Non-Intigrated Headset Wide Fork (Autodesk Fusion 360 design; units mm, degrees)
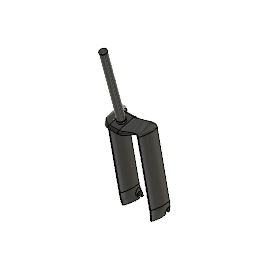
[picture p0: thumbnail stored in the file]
sketch "Sketch1" plane through (0, 0, 0) normal (0, 0, 1) x axis (1, 0, 0)
  circle C1 centre (0, 0) radius 15
  circle C2 centre (0, 0) radius 14.3
  circle C3 centre (0, 0) radius 17
  circle C4 centre (0, 0) radius 12.8
  point P1 (0, 0)
  point P2 (0, 0)
  coincident P1 P2
  concentric C1 C2
  concentric C1 C3
  dimension "d1" diameter C1 = 30
  dimension "d2" diameter C2 = 28.6
  dimension "d3" diameter C3 = 34
  dimension "d76" = -1.5
extrude "Extrude1" new body sketch "Sketch1" profile of C2 along normal blind 300
extrude "Extrude2" add sketch "Sketch1" profile of C1 C2 along normal blind 10
extrude "Extrude3" add sketch "Sketch1" profile of C1 C2 C3 against normal blind 5
sketch "Sketch2" plane through (0, 0, 0) normal (1, 0, 0) x axis (0, 1, 0)
  line L1 (0, -374) -> (0, -5)
  line L2 (35, -374) -> (0, -374)
  point P2 (0, -5)
  point P3 (0, -374)
  point P4 (35, -374)
  vertical L1
  perpendicular L1 L2
  dimension "d10" distance P2 P3 = 369
  dimension "d11" distance P3 P4 = 35
sketch "Sketch3" plane through (0, 0, 0) normal (0, 1, 0) x axis (1, 0, 0)
  line L1 (57.5, 177.3414) -> (57.5, 29.6202)
  line L2 (-57.5, 177.3414) -> (-57.5, 29.6202)
  line L3 (57.5, 320.1385) -> (57.5, 177.3414)
  line L4 (-57.5, 320.1385) -> (-57.5, 177.3414)
  line L5 (-32.5, 5) -> (32.5, 5)
  arc A1 centre (32.5, 29.6202) radius 25 between (57.5, 29.6202) and (32.5, 5)
  arc A2 centre (-32.5, 29.6202) radius 25 between (-32.5, 5) and (-57.5, 29.6202)
  arc A3 centre (112.9167, 320.1385) radius 170.4167 between (-57.5, 320.1385) and (-50, 369.3789)
  arc A4 centre (-112.9167, 320.1385) radius 170.4167 between (50, 369.3789) and (57.5, 320.1385)
  point P2 (-50, 369.3789)
  point P3 (50, 369.3789)
  point P5 (57.5, 177.3414)
  point P6 (-57.5, 177.3414)
  tangent A1 L1
  tangent A2 L2
  tangent L4 A3
  tangent L3 A4
  tangent A2 L5
  dimension "d12" distance P2 P3 = 100
  dimension "d13" distance P5 P6 = 115
work_plane "WorkPlane1" AlongDistance -30
sketch "Sketch4" plane through (0, 0, -30) normal (0, 0, 1) x axis (1, 0, 0)
  line L1 (61.75, -26.0181) -> (65.75, -26.0181)
  arc A1 centre (63.75, 47.577) radius 6.4049 clockwise from (57.5, 48.977) to (70, 48.977)
  arc A2 centre (-64.0291, 18.9545) radius 137.3505 clockwise from (70, 48.977) to (65.75, -26.0181)
  arc A3 centre (191.5291, 18.9545) radius 137.3505 clockwise from (61.75, -26.0181) to (57.5, 48.977)
  point P5 (65.75, -26.0181)
  point P6 (61.75, -26.0181)
  tangent A1 A2
  tangent A1 A3
  dimension "d21" distance P5 P6 = 4
move "Move1"
sweep "Sweep1" sketch "Sketch4" TwistAngle 0 TaperAngle 0
move "Move2"
sketch "Sketch5" plane through (0, 0, 0) normal (1, 0, 0) x axis (0, 1, 0)
  line L1 (30.0985, 8.2412) -> (-32.6867, -8.582)
  line L2 (32.5, -0.1704) -> (-1.2941, -0.1704)
  arc A1 centre (32.4028, -0.3584) radius 8.903 clockwise from (30.0985, 8.2412) to (40, -5)
  arc A2 centre (-30.6379, -16.2282) radius 7.9159 clockwise from (-37.7927, -19.615) to (-32.6867, -8.582)
  arc A3 centre (-30.9882, 158.5102) radius 178.2552 clockwise from (40, -5) to (-37.7927, -19.615)
  point P4 (-1.2941, -0.1704)
  point P2 (-32.6867, -8.582)
  point P3 (30.0985, 8.2412)
  midpoint L1 P4
  horizontal L2
  tangent L1 A1
  tangent L1 A2
  dimension "d28" distance P2 P3 = 65
  dimension "d29" angle L1 L2 = 15
extrude "Extrude4" add sketch "Sketch5" profile of L1 A1 A2 A3 along normal blind 20
loft "Loft1"
sketch "Sketch6" plane through (0, 0, 0) normal (1, 0, 0) x axis (0, 1, 0)
  line L1 (95.5042, -361.4266) -> (0, -5)
  line L2 (369, -5) -> (0, -5)
  line L3 (124.482, -353.6621) -> (95.5042, -361.4266)
  line L4 (126.6058, -378.9749) -> (120.1353, -354.8267)
  line L5 (135.3147, -376.7052) -> (128.8442, -352.5571)
  line L6 (153.8442, -352.5571) -> (128.8442, -352.5571)
  line L7 (126.6058, -378.9749) -> (135.3147, -376.7052)
  line L8 (120.8103, -380.5278) -> (114.3398, -356.3797)
  line L9 (141.0947, -375.0926) -> (134.6242, -350.9445)
  line L10 (120.8103, -380.5278) -> (141.0947, -375.0926)
  circle C1 centre (124.482, -353.6621) radius 4.5
  circle C2 centre (124.482, -353.6621) radius 10.5
  point P5 (124.482, -353.6621)
  point P6 (124.482, -353.6621)
  point P8 (120.1353, -354.8267)
  point P10 (128.8442, -352.5571)
  point P13 (114.3398, -356.3797)
  point P15 (134.6242, -350.9445)
  point P2 (0, -5)
  point P3 (95.5042, -361.4266)
  point P9 (126.6058, -378.9749)
  point P11 (135.3147, -376.7052)
  point P14 (120.8103, -380.5278)
  point P16 (141.0947, -375.0926)
  horizontal L2
  perpendicular L1 L3
  coincident P5 P6
  concentric C1 C2
  coincident C1 P8
  coincident L3 P8
  perpendicular L3 L4
  horizontal L6
  coincident C1 P10
  coincident L3 P13
  coincident C2 P13
  perpendicular L3 L8
  coincident C2 P15
  perpendicular L3 L9
  perpendicular L8 L10
  dimension "d38" distance P2 P3 = 369
  dimension "d39" angle L1 L2 = 75
  dimension "d40" distance P3 P5 = 30
  dimension "d41" diameter C1 = 9
  dimension "d42" diameter C2 = 21
  dimension "d43" distance P8 P9 = 25
  dimension "d44" angle L5 L6 = 75
  dimension "d45" distance P10 P11 = 25
  dimension "d50" distance P13 P14 = 25
  dimension "d51" distance P15 P16 = 25
extrude "Extrude5" cut sketch "Sketch6" profile of C1 C2 L4 L5 L7 along normal blind 80
extrude "Extrude6" cut sketch "Sketch6" profile of L3 C1 C2 L4 L5 L8 L9 L10 along normal blind 55
sketch "Sketch7" plane through (0, 0, 0) normal (1, 0, 0) x axis (0, 1, 0)
  line L1 (120.8103, -380.5278) -> (114.3398, -356.3797)
  line L2 (126.6058, -378.9749) -> (120.1353, -354.8267)
  line L3 (120.8103, -380.5278) -> (141.0947, -375.0926)
  line L4 (126.6058, -378.9749) -> (135.3147, -376.7052)
  line L5 (135.3147, -376.7052) -> (128.8442, -352.5571)
  line L6 (141.0947, -375.0926) -> (134.6242, -350.9445)
  circle C1 centre (124.482, -353.6621) radius 10.5
  circle C2 centre (124.482, -353.6621) radius 4.5
  point P11 (124.482, -353.6621)
  point P12 (124.482, -353.6621)
  point P9 (120.1353, -354.8267)
  point P7 (128.8442, -352.5571)
  point P4 (114.3398, -356.3797)
  point P2 (134.6242, -350.9445)
  point P6 (126.6058, -378.9749)
  point P10 (135.3147, -376.7052)
  point P3 (120.8103, -380.5278)
  point P5 (141.0947, -375.0926)
  coincident P11 P12
  concentric C1 C2
  coincident P9 C2
  coincident P7 C2
  coincident P4 C1
  coincident P2 C1
  perpendicular L1 L3
  dimension "d54" diameter C2 = 9
  dimension "d55" diameter C1 = 21
  dimension "d56" distance P6 P9 = 25
  dimension "d57" distance P7 P10 = 25
  dimension "d58" distance P3 P4 = 25
  dimension "d59" distance P2 P5 = 25
extrude "Extrude7" cut sketch "Sketch7" profile of L1 L2 L3 C1 L5 C2 L6 along normal blind 10 and against normal blind 5
extrude "Extrude8" add of existing geometry blind 5
fillet "Fillet3" radius 20
fillet "Fillet4" radius 2
work_plane "WorkPlane2" AlongDistance -368
split "Split1"
fillet "Fillet5" radius 2.5
fillet "Fillet6" radius 1
mirror "Mirror1" mirrorStitchTolerance 0.1
sketch "Sketch8" plane through (0, 0, 0) normal (1, 0, 0) x axis (0, 1, 0)
step "TorusPrimitive" MinorDiameter 28 MajorDiameter 650
sketch "Sketch10" plane through (0, -77.6898, 289.9423) normal (0, -0.2588, 0.9659) x axis (1, 0, 0)
  circle C1 centre (0, -1.2941) radius 13
  arc A1 centre (0, -1.2941) radius 14.3 clockwise from (14.3, -1.2941) to (-14.3, -1.2941)
  arc A2 centre (0, -1.2941) radius 14.3 clockwise from (-14.3, -1.2941) to (14.3, -1.2941)
  dimension "d78" diameter C1 = 26
extrude "Extrude9" cut sketch "Sketch10" profile of C1 against normal blind 295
